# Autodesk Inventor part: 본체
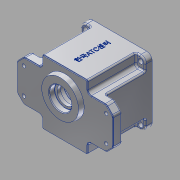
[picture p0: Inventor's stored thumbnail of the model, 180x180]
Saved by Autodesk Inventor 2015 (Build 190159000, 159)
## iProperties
Created: 2016-02
Part Number: 본체
Material: Aluminum 6061
Document SubType Name: Modeling
Designer: Administrator
Density: 2.7 g/cm^3
Appearance: Aluminum - Flat
Mass: 873.75 g
Surface Area: 761.343 cm^2
Volume: 323.611 cm^3
Author: Administrator
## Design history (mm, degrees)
sketch "Sketch2"
  geometry: L1 (-33, 30)-(-33, 47); L2 (-33, 47)-(33, 47); L3 (33, 47)-(33, 30); L4 (33, 30)-(57.929, 30); L5 (70, 17.929)-(70, -17.929); L6 (57.929, -30)-(33, -30); L7 (33, -30)-(33, -47); L8 (33, -47)-(-33, -47); L9 (-33, -47)-(-33, -30); L10 (-33, -30)-(-57.929, -30); L11 (-70, -17.929)-(-70, 17.929); L12 (-57.929, 30)-(-33, 30); L13 (-68.536, 21.464)-(-61.464, 28.536); L14 (-68.536, -21.464)-(-61.464, -28.536); L15 (61.464, -28.536)-(68.536, -21.464); L16 (68.536, 21.464)-(61.464, 28.536); A1 r 5 centre (57.929, -25) between (57.929, -30) and (61.464, -28.536); A2 r 5 centre (65, -17.929) between (68.536, -21.464) and (70, -17.929); A3 r 5 centre (65, -17.929) between (68.536, -21.464) and (70, -17.929); A4 r 5 centre (65, 17.929) between (70, 17.929) and (68.536, 21.464); A5 r 5 centre (57.929, 25) between (61.464, 28.536) and (57.929, 30); A6 r 5 centre (-57.929, 25) between (-57.929, 30) and (-61.464, 28.536); A7 r 5 centre (-65, 17.929) between (-68.536, 21.464) and (-70, 17.929); A8 r 5 centre (-57.929, -25) between (-61.464, -28.536) and (-57.929, -30); A9 r 5 centre (-65, -17.929) between (-70, -17.929) and (-68.536, -21.464); 13 further points
  constraints: 32 end point, 26 point on line, 18 point on circle, 18 tangent, 11 perpendicular, 9 centre point, 8 equal radius, 1 vertical
  dimensions: "d8" = 66 distance between parallel lines of L3 L1; "d9" = 66 distance between parallel lines of L7 L9; "d10" = 33 distance from line of point (0, 0) L1; "d11" = 33 distance from line of point (0, 0) L9; "d12" = 60 distance between parallel lines of L6 L4; "d13" = 60 distance of point (-70, -30) point (-70, 30); "d14" = 30 distance from line of point (0, 0) L12; "d15" = 30 distance from line of point (0, 0) L4; "d16" = 94 distance between parallel lines of L8 L2; "d17" = 47 distance from line of point (0, 0) L2; "d18" = 140 distance between parallel lines of L5 L11; "d19" = 70 distance from line of point (0, 0) L11; "d20" = 10 distance of point (-70, 20) point (-70, 30); "d21" = 10 distance of point (-60, 30) point (-70, 30) (= d20); "d22" = 10 distance of point (-70, -20) point (-70, -30) (= d20); "d23" = 10 distance of point (-60, -30) point (-70, -30) (= d22); "d24" = 10 distance of point (60, -30) point (70, -30) (= d20); "d25" = 10 distance of point (70, -20) point (70, -30) (= d24); "d26" = 10 distance of point (70, 20) point (70, 30) (= d20); "d27" = 10 distance of point (60, 30) point (70, 30) (= d26); "d127" = 5 radius of A1
extrude "Extrusion1" new body sketch "Sketch2" distance "d28" = 13; taper "d29" = 0 deg
sketch "Sketch3"
  geometry: L1 (39, 47)-(-39, 47); L2 (-47, 39)-(-47, -39); L3 (-39, -47)-(39, -47); L4 (47, -39)-(47, 39); L5 (47, 47)-(-47, -47); L6 (-47, 47)-(47, -47); A1 r 8 centre (39, -39) between (39, -47) and (47, -39); A2 r 8 centre (39, 39) between (47, 39) and (39, 47); A3 r 8 centre (-39, 39) between (-39, 47) and (-47, 39); A4 r 8 centre (-39, -39) between (-47, -39) and (-39, -47); 1 further point
  constraints: 12 end point, 8 point on circle, 8 point on line, 8 tangent, 4 centre point, 3 equal radius, 2 midpoint, 2 parallel, 1 horizontal, 1 perpendicular
  dimensions: "d30" = 94 distance of L5.end L6.end; "d31" = 94 distance of L6.start L5.end; "d32" = 8 radius of A1
extrude "Extrusion2" join sketch "Sketch3" distance "d33" = 67; taper "d34" = 0 deg
sketch "Sketch4"
  geometry: L1 (33, 30)-(47, 30) reference; L2 (47, 30)-(47, 39) reference; L3 (39, 47)-(33, 47) reference; L4 (33, 47)-(33, 30) reference; L5 (-47, 30)-(-33, 30) reference; L6 (-33, 30)-(-33, 47) reference; L7 (-33, 47)-(-39, 47) reference; L8 (-47, 39)-(-47, 30) reference; L9 (-33, -47)-(-33, -30) reference; L10 (-33, -30)-(-47, -30) reference; L11 (-47, -30)-(-47, -39) reference; L12 (-39, -47)-(-33, -47) reference; L13 (33, -30)-(33, -47) reference; L14 (33, -47)-(39, -47) reference; L15 (47, -39)-(47, -30) reference; L16 (47, -30)-(33, -30) reference; A1 r 8 centre (39, 39) between (47, 39) and (39, 47) reference; A2 r 8 centre (-39, 39) between (-39, 47) and (-47, 39) reference; A3 r 8 centre (-39, -39) between (-47, -39) and (-39, -47) reference; A4 r 8 centre (39, -39) between (39, -47) and (47, -39) reference; 1 further point
extrude "Extrusion3" cut sketch "Sketch4" distance "d35" = 57; taper "d36" = 0 deg
sketch "Sketch5"
  geometry: A1 r 36 centre (0, 0) between (-36, 0) and (36, 0); A2 r 4 centre (36, 0) between (35.852, 3.997) and (35.852, -3.997); A3 r 4 centre (-36, 0) between (-35.852, -3.997) and (-35.852, 3.997); A4 r 3.5 centre (35.722, -7.495) between (39.148, -8.214) and (35.778, -3.995); A5 r 3.5 centre (35.722, 7.495) between (35.778, 3.995) and (39.088, 8.456); A6 r 3.5 centre (-35.722, -7.495) between (-35.778, -3.995) and (-39.148, -8.214); A7 r 3.5 centre (-35.722, 7.495) between (-39.148, 8.214) and (-35.778, 3.995); A8 r 40 centre (0, 0) between (39.148, 8.214) and (-39.148, 8.214); A9 r 40 centre (0, 0) between (-39.148, -8.214) and (39.148, -8.214); 1 further point
  constraints: 27 point on circle, 9 centre point, 8 tangent, 2 coincident, 2 horizontal alignment
  dimensions: "d53" = 72 diameter of A1; "d54" = 4 radius of A2; "d55" = 4 radius of A3; "d56" = 3.5 radius of A4; "d57" = 3.5 radius of A5; "d58" = 3.5 radius of A6; "d60" = 40 radius of A9; "d61" = 40 radius of A8; "d62" = 3.5 radius of A7
extrude "Extrusion4" cut sketch "Sketch5" distance "d38" = 71; taper "d39" = 0 deg
sketch "Sketch6"
  geometry: C1 r 28 at (0, 11); 1 further point
  constraints: 1 centre point, 1 vertical alignment
  dimensions: "d40" = 56 diameter of C1; "d41" = 11 distance of point (0, 0) C1.centre
extrude "Extrusion5" join sketch "Sketch6" distance "d42" = 7; taper "d43" = -10 deg
sketch "Sketch10"
  geometry: C1 r 43 at (0, 0); 1 further point
  constraints: 1 centre point, 1 coincident
  dimensions: "d50" = 86 diameter of C1
extrude "Extrusion7" cut sketch "Sketch10" distance "d51" = 9; taper "d52" = 0 deg
sketch "Sketch11"
  geometry: A1 r 4 centre (36, 0) between (35.852, 3.997) and (35.852, -3.997) reference; A2 r 4 centre (-36, 0) between (-35.852, -3.997) and (-35.852, 3.997) reference; 3 further points
  constraints: 2 coincident
hole "Hole1" sketch "Sketch11" at (36, 0), (-36, 0) diameter "d63" = 3.242; stored, may be unused: countersink angle "d67" = 90 deg, drill point angle "d69" = 118 deg; dims "d64" = 7, "d65" = 4, "d66" = 2, "d68" = 9
sketch "Sketch12"
  geometry: C1 r 26.766 at (0, -11) reference; C2 r 21 at (0, -11); C3 r 15 at (0, 20); 1 further point
  constraints: 2 centre point, 1 coincident, 1 vertical alignment
  dimensions: "d72" = 21 radius of C2; "d73" = 15 radius of C3; "d74" = 20 distance of C3.centre point (0, 0)
extrude "Extrusion8" join sketch "Sketch12" distance "d75" = 7; taper "d76" = 0 deg
sketch "Sketch13"
  geometry: A1 r 15 centre (0, 20) between (8.978, 7.984) and (-8.978, 7.984) reference; 2 further points
  constraints: 1 coincident
hole "Hole2" sketch "Sketch13" at (0, 20) diameter "d77" = 19; stored, may be unused: countersink angle "d81" = 90 deg, drill point angle "d83" = 0 deg; dims "d78" = 7, "d79" = 22, "d80" = 7, "d82" = 8
sketch "Sketch14"
  geometry: A1 r 21 centre (0, -11) between (-8.978, 7.984) and (8.978, 7.984) reference; 2 further points
  constraints: 1 coincident
hole "Hole3" sketch "Sketch14" at (0, -11) diameter "d84" = 25; stored, may be unused: countersink angle "d88" = 90 deg, drill point angle "d90" = 0 deg; dims "d85" = 7, "d86" = 35, "d87" = 10, "d89" = 15
sketch "Sketch15"
  geometry: C1 r 26.766 at (0, 0) reference; 2 further points
  constraints: 1 coincident
hole "Hole4" sketch "Sketch15" at (0, 0) diameter "d91" = 32; stored, may be unused: countersink angle "d95" = 90 deg, drill point angle "d97" = 0 deg; dims "d92" = 7, "d93" = 35, "d94" = 10, "d96" = 8
sketch "Sketch17"
  geometry: 5 further points
  constraints: 2 horizontal alignment, 2 vertical alignment
  dimensions: "d102" = 120 distance of point (-60, -19) point (60, -19); "d103" = 60 horizontal distance of point (0, 0) point (60, -19); "d104" = 38 distance of point (-60, 19) point (-60, -19); "d105" = 19 vertical distance of point (0, 0) point (-60, -19)
hole "Hole5" sketch "Sketch17" at (60, -19), (60, 19), (-60, -19), (-60, 19) diameter "d106" = 5; stored, may be unused: countersink angle "d110" = 90 deg, drill point angle "d112" = 0 deg; dims "d107" = 7, "d108" = 9, "d109" = 4, "d111" = 8
sketch "Sketch18"
  geometry: 5 further points
  constraints: 2 horizontal alignment, 2 vertical alignment
  dimensions: "d113" = 80 distance of point (40, 40) point (-40, 40); "d114" = 40 horizontal distance of point (0, 0) point (-40, 40); "d115" = 80 distance of point (40, -40) point (40, 40); "d116" = 40 horizontal distance of point (0, 0) point (40, 40)
hole "Hole6" sketch "Sketch18" at (-40, 40), (-40, -40), (40, 40), (40, -40) diameter "d117" = 7; stored, may be unused: countersink angle "d121" = 90 deg, drill point angle "d123" = 0 deg; dims "d118" = 7, "d119" = 9, "d120" = 4, "d122" = 8
sketch "Sketch19" dims "d8" = 66, "d9" = 66, "d10" = 33, "d11" = 33, "d12" = 60, "d13" = 60, "d14" = 30, "d15" = 30, "d16" = 94, "d17" = 47, "d18" = 140, "d19" = 70, "d20" = 10, "d21" = 10 (= d20), "d22" = 10 (= d20), "d23" = 10 (= d22), "d24" = 10 (= d20), "d25" = 10 (= d24), "d26" = 10 (= d20), "d27" = 10 (= d26), "d127" = 5
  geometry: L1 (0, 0)-(66, 0) reference; L2 (-6, 80)-(72, 80) reference; 3 further points
  constraints: 1 midpoint, 1 vertical alignment, 1 other
  dimensions: "d124" = 40 distance from line of L2 point (33, 40)
emboss "Emboss1" sketch "Sketch19" dims "d8" = 66, "d9" = 66, "d10" = 33, "d11" = 33, "d12" = 60, "d13" = 60, "d14" = 30, "d15" = 30, "d16" = 94, "d17" = 47, "d18" = 140, "d19" = 70, "d20" = 10, "d21" = 10 (= d20), "d22" = 10 (= d20), "d23" = 10 (= d22), "d24" = 10 (= d20), "d25" = 10 (= d24), "d26" = 10 (= d20), "d27" = 10 (= d26), "d125" = 0.5, "d126" = 0, "d127" = 5
fillet "Fillet1" dims "d128" = 5
chamfer "Chamfer1" distance "d129" = 1; stored, may be unused: second distance "d130" = 2, angle "d131" = 45 deg
fillet "Fillet2" dims "d132" = 0.3
fillet "Fillet3" dims "d133" = 2
fillet "Fillet4" dims "d134" = 2
sketch "Sketch20"
  geometry: L1 (-31, 47)-(31, 47) reference; L2 (-33, 35)-(-33, 45) reference; L3 (-57.929, 30)-(-38, 30) reference; L4 (-68.536, 21.464)-(-61.464, 28.536) reference; L5 (-70, -17.929)-(-70, 17.929) reference; L6 (-61.464, -28.536)-(-68.536, -21.464) reference; L7 (-38, -30)-(-57.929, -30) reference; L8 (-33, -45)-(-33, -35) reference; L9 (31, -47)-(-31, -47) reference; L10 (33, 45)-(33, 35) reference; L11 (38, 30)-(57.929, 30) reference; L12 (61.464, 28.536)-(68.536, 21.464) reference; L13 (70, 17.929)-(70, -17.929) reference; L14 (68.536, -21.464)-(61.464, -28.536) reference; L15 (57.929, -30)-(38, -30) reference; L16 (33, -35)-(33, -45) reference; L17 (31, 46)-(-31, 46); L18 (-32, 45)-(-32, 35); L19 (-38, 29)-(-57.929, 29); L20 (-60.757, 27.828)-(-67.828, 20.757); L21 (-69, 17.929)-(-69, -17.929); L22 (-67.828, -20.757)-(-60.757, -27.828); L23 (-57.929, -29)-(-38, -29); L24 (-32, -35)-(-32, -45); L25 (-31, -46)-(31, -46); L26 (32, -45)-(32, -35); L27 (38, -29)-(57.929, -29); L28 (60.757, -27.828)-(67.828, -20.757); L29 (69, -17.929)-(69, 17.929); L30 (67.828, 20.757)-(60.757, 27.828); L31 (57.929, 29)-(38, 29); L32 (32, 35)-(32, 45); A1 r 2 centre (-31, 45) between (-31, 47) and (-33, 45) reference; A2 r 5 centre (-38, 35) between (-38, 30) and (-33, 35) reference; A3 r 5 centre (-57.929, 25) between (-57.929, 30) and (-61.464, 28.536) reference; A4 r 5 centre (-65, 17.929) between (-68.536, 21.464) and (-70, 17.929) reference; A5 r 5 centre (-65, -17.929) between (-70, -17.929) and (-68.536, -21.464) reference; A6 r 5 centre (-57.929, -25) between (-61.464, -28.536) and (-57.929, -30) reference; A7 r 5 centre (-38, -35) between (-33, -35) and (-38, -30) reference; A8 r 2 centre (-31, -45) between (-33, -45) and (-31, -47) reference; A9 r 5 centre (38, 35) between (33, 35) and (38, 30) reference; A10 r 2 centre (31, 45) between (33, 45) and (31, 47) reference; A11 r 5 centre (57.929, 25) between (61.464, 28.536) and (57.929, 30) reference; A12 r 5 centre (65, 17.929) between (70, 17.929) and (68.536, 21.464) reference; A13 r 5 centre (65, -17.929) between (68.536, -21.464) and (70, -17.929) reference; A14 r 5 centre (57.929, -25) between (57.929, -30) and (61.464, -28.536) reference; A15 r 5 centre (38, -35) between (38, -30) and (33, -35) reference; A16 r 2 centre (31, -45) between (31, -47) and (33, -45) reference; A17 r 1 centre (-31, 45) between (-31, 46) and (-32, 45); A18 r 6 centre (-38, 35) between (-38, 29) and (-32, 35); A19 r 4 centre (-57.929, 25) between (-57.929, 29) and (-60.757, 27.828); A20 r 4 centre (-65, 17.929) between (-67.828, 20.757) and (-69, 17.929); A21 r 4 centre (-65, -17.929) between (-69, -17.929) and (-67.828, -20.757); A22 r 4 centre (-57.929, -25) between (-60.757, -27.828) and (-57.929, -29); A23 r 6 centre (-38, -35) between (-32, -35) and (-38, -29); A24 r 1 centre (-31, -45) between (-32, -45) and (-31, -46); A25 r 1 centre (31, -45) between (31, -46) and (32, -45); A26 r 6 centre (38, -35) between (38, -29) and (32, -35); A27 r 4 centre (57.929, -25) between (57.929, -29) and (60.757, -27.828); A28 r 4 centre (65, -17.929) between (67.828, -20.757) and (69, -17.929); A29 r 4 centre (65, 17.929) between (69, 17.929) and (67.828, 20.757); A30 r 4 centre (57.929, 25) between (60.757, 27.828) and (57.929, 29); A31 r 6 centre (38, 35) between (32, 35) and (38, 29); A32 r 1 centre (31, 45) between (32, 45) and (31, 46); 1 further point
  constraints: 32 end point, 32 point on circle, 16 centre point, 31 other
  dimensions: "d135" = 1 distance between parallel lines of L1 L17
extrude "Extrusion9" cut sketch "Sketch20" distance "d136" = 1; taper "d137" = 0 deg
fillet "Fillet5" dims "d138" = 2
fillet "Fillet6" dims "d139" = 3
fillet "Fillet7" dims "d140" = 2
body "Solid1"
node "Projected Loop1"
node "Projected Loop2"
node "Projected Loop3"
node "Projected Loop4"
other parameters: "d59" = 3.5
